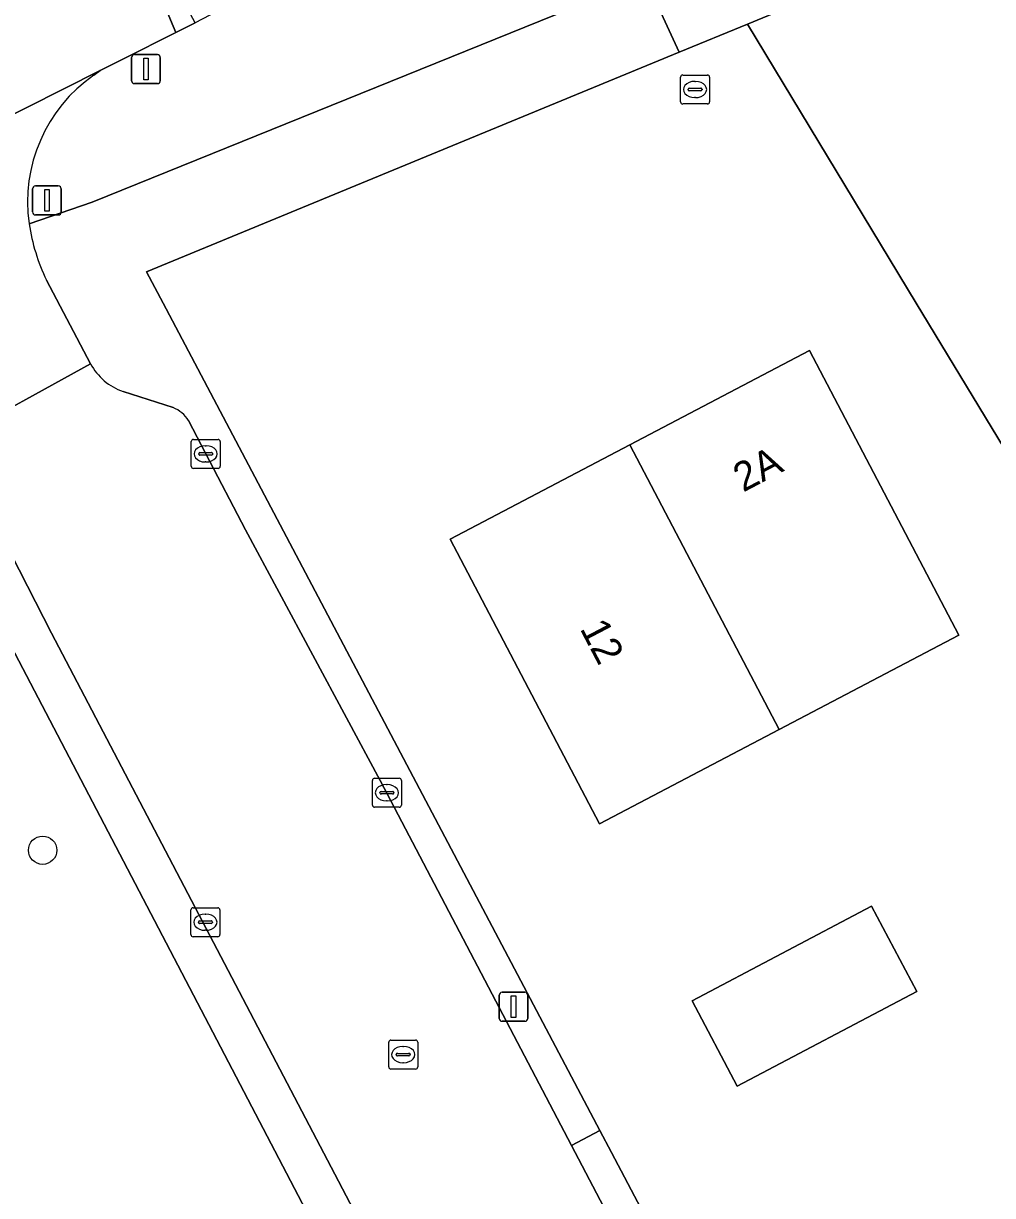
# Model space of a CAD drawing. Extents: x 162879 to 165540, y 384011 to 385181.
# Drawn here: x 163066.68 to 163100.12, y 384219.21 to 384259.65 of the extents above; entities that cross this region are included whole.
import ezdxf

# ---------------------------------------------------------------- set-up
doc = ezdxf.new("R2010")
doc.units = 0
for name, color, linetype in [('IMGEO_Boom', 7, 'Continuous'), ('IMGEO_Brandkraan', 7, 'Continuous'), ('IMGEO_Erf', 7, 'Continuous'), ('IMGEO_Groenvoorziening', 7, 'Continuous'), ('IMGEO_Kolk', 7, 'Continuous'), ('IMGEO_Lichtmast', 7, 'Continuous'), ('IMGEO_Loofbos', 7, 'Continuous'), ('IMGEO_Pand', 7, 'Continuous'), ('IMGEO_Pand_nummerreeks', 7, 'Continuous'), ('IMGEO_Rijbaan_lokaal_gesloten', 7, 'Continuous'), ('IMGEO_Rijbaan_lokaal_open', 7, 'Continuous'), ('IMGEO_Rioolput', 7, 'Continuous'), ('IMGEO_Verkeersbordpaal', 7, 'Continuous'), ('IMGEO_Voetpad_open', 7, 'Continuous')]:
    doc.layers.add(name, color=color, linetype=linetype)

msp = doc.modelspace()

# ---------------------------------------------------------------- linework, layer by layer
at = {"layer": 'IMGEO_Boom'}
msp.add_circle((163067.341, 384231.127), 0.489, dxfattribs=at)
at = {"layer": 'IMGEO_Brandkraan'}
for p, q in [((163089.356, 384256.945), (163089.356, 384257.797)), ((163089.431, 384257.871), (163090.283, 384257.871)), ((163089.844, 384257.651), (163089.869, 384257.651)), ((163090.357, 384257.797), (163090.357, 384256.945)), ((163089.615, 384257.365), (163089.615, 384257.377)), ((163090.053, 384257.328), (163089.655, 384257.328)), ((163089.658, 384257.414), (163090.056, 384257.414)), ((163090.099, 384257.377), (163090.099, 384257.365)), ((163090.283, 384256.871), (163089.431, 384256.871)), ((163089.867, 384257.091), (163089.842, 384257.091))]:
    msp.add_line(p, q, dxfattribs=at)
for points in [[(163089.356, 384256.945), (163089.356, 384257.797)], [(163089.431, 384257.871), (163090.283, 384257.871)], [(163090.357, 384257.797), (163090.357, 384256.945)], [(163090.283, 384256.871), (163089.431, 384256.871)]]:
    msp.add_lwpolyline(points, dxfattribs=at)
for centre, radius, start, end in [((163089.433, 384257.795), 0.0765, 91.552, 178.448), ((163089.433, 384257.795), 0.0765, 91.552, 178.448), ((163090.281, 384257.795), 0.0765, 1.552, 88.448), ((163090.281, 384257.795), 0.0765, 1.552, 88.448), ((163089.655, 384257.374), 0.0403, 85.8775, 175.7526), ((163089.652, 384257.364), 0.0366, 178.938, 274.7102), ((163090.056, 384257.371), 0.043, 264.8664, 352.4533), ((163090.06, 384257.376), 0.0386, 1.7309, 96.639), ((163089.433, 384256.947), 0.0765, 181.552, 268.448), ((163089.433, 384256.947), 0.0765, 181.552, 268.448), ((163090.281, 384256.947), 0.0765, 271.552, 358.448), ((163090.281, 384256.947), 0.0765, 271.552, 358.448)]:
    msp.add_arc(centre, radius, start, end, dxfattribs=at)
for centre, major_axis, ratio, start_param, end_param in [((163089.843, 384257.371), (-0.387, 0.002), 0.722429, 4.712389, 7.853982), ((163089.868, 384257.371), (-0.39, 0.002), 0.717154, 1.570796, 4.712389)]:
    msp.add_ellipse(centre, major_axis=major_axis, ratio=ratio, start_param=start_param, end_param=end_param, dxfattribs=at)
at = {"layer": 'IMGEO_Erf'}
for points in [[(163102.346, 384234.16), (163102.432, 384234.205), (163100.651, 384237.577), (163103.837, 384239.259), (163105.617, 384235.887), (163105.946, 384236.061), (163097.491, 384250), (163091.662, 384259.624), (163089.311, 384258.655), (163070.929, 384251.083), (163071.501, 384250), (163086.567, 384221.458), (163086.969, 384220.697), (163092.948, 384209.374), (163113.929, 384219.667), (163114.138, 384219.769), (163111.612, 384224.762), (163108.882, 384230.159), (163105.424, 384228.333)], [(163092.76, 384235.29), (163086.556, 384232.036), (163081.402, 384241.862), (163087.605, 384245.115), (163093.808, 384248.369), (163098.962, 384238.543)], [(163097.505, 384226.251), (163091.306, 384222.983), (163089.754, 384225.927), (163095.95, 384229.2)]]:
    msp.add_lwpolyline(points, close=True, dxfattribs=at)
at = {"layer": 'IMGEO_Groenvoorziening'}
for points in [[(163088.136, 384261.216), (163086.443, 384265.31), (163074.285, 384260.44), (163073.374, 384260.069), (163072.602, 384259.676), (163071.935, 384259.339), (163070.11, 384258.418), (163069.325, 384258.023), (163069.104, 384257.867)], [(163066.874, 384252.737), (163069.054, 384253.483), (163088.136, 384261.216)]]:
    msp.add_lwpolyline(points, dxfattribs=at)
msp.add_lwpolyline([(163062.352, 384245.606), (163049.969, 384239.189), (163051.264, 384236.696), (163047.577, 384234.747), (163057.039, 384216.873), (163041.173, 384208.482), (163044.864, 384201.274), (163071.063, 384215.12), (163072.147, 384212.977), (163072.222, 384213.017), (163074.076, 384209.512), (163077.812, 384211.477), (163079.73, 384207.94), (163081.516, 384208.957)], close=True, dxfattribs=at)
msp.add_arc((163072.162, 384253.488), 5.341, 124.9288, 188.0822, dxfattribs=at)
at = {"layer": 'IMGEO_Kolk'}
for p, q in [((163072.468, 384244.375), (163072.468, 384245.227)), ((163072.543, 384245.301), (163073.395, 384245.301)), ((163073.469, 384245.227), (163073.469, 384244.375)), ((163072.727, 384244.795), (163072.727, 384244.807)), ((163073.165, 384244.758), (163072.767, 384244.758)), ((163072.77, 384244.844), (163073.168, 384244.844)), ((163072.956, 384245.081), (163072.981, 384245.081)), ((163073.211, 384244.807), (163073.211, 384244.795)), ((163073.395, 384244.301), (163072.543, 384244.301)), ((163072.979, 384244.521), (163072.954, 384244.521)), ((163078.722, 384232.684), (163078.722, 384233.536)), ((163078.797, 384233.61), (163079.649, 384233.61)), ((163079.21, 384233.39), (163079.235, 384233.39)), ((163079.723, 384233.536), (163079.723, 384232.684)), ((163078.981, 384233.104), (163078.981, 384233.116)), ((163079.419, 384233.067), (163079.021, 384233.067)), ((163079.024, 384233.153), (163079.422, 384233.153)), ((163079.465, 384233.116), (163079.465, 384233.104)), ((163079.649, 384232.61), (163078.797, 384232.61)), ((163079.233, 384232.83), (163079.208, 384232.83)), ((163072.458, 384228.218), (163072.458, 384229.07)), ((163072.533, 384229.144), (163073.385, 384229.144)), ((163072.946, 384228.924), (163072.971, 384228.924)), ((163073.459, 384229.07), (163073.459, 384228.218)), ((163072.717, 384228.638), (163072.717, 384228.65)), ((163073.155, 384228.601), (163072.757, 384228.601)), ((163072.76, 384228.687), (163073.158, 384228.687)), ((163073.201, 384228.65), (163073.201, 384228.638)), ((163073.385, 384228.144), (163072.533, 384228.144)), ((163072.969, 384228.364), (163072.944, 384228.364))]:
    msp.add_line(p, q, dxfattribs=at)
for points in [[(163072.468, 384244.375), (163072.468, 384245.227)], [(163072.543, 384245.301), (163073.395, 384245.301)], [(163073.469, 384245.227), (163073.469, 384244.375)], [(163073.395, 384244.301), (163072.543, 384244.301)], [(163078.722, 384232.684), (163078.722, 384233.536)], [(163078.797, 384233.61), (163079.649, 384233.61)], [(163079.723, 384233.536), (163079.723, 384232.684)], [(163079.649, 384232.61), (163078.797, 384232.61)], [(163072.458, 384228.218), (163072.458, 384229.07)], [(163072.533, 384229.144), (163073.385, 384229.144)], [(163073.459, 384229.07), (163073.459, 384228.218)], [(163073.385, 384228.144), (163072.533, 384228.144)]]:
    msp.add_lwpolyline(points, dxfattribs=at)
for centre, radius, start, end in [((163072.545, 384245.225), 0.0765, 91.552, 178.448), ((163072.545, 384245.225), 0.0765, 91.552, 178.448), ((163073.393, 384245.225), 0.0765, 1.552, 88.448), ((163073.393, 384245.225), 0.0765, 1.552, 88.448), ((163072.767, 384244.804), 0.0403, 85.8775, 175.7526), ((163072.764, 384244.794), 0.0366, 178.938, 274.7102), ((163073.168, 384244.801), 0.043, 264.8664, 352.4533), ((163073.172, 384244.806), 0.0386, 1.7309, 96.639), ((163072.545, 384244.377), 0.0765, 181.552, 268.448), ((163072.545, 384244.377), 0.0765, 181.552, 268.448), ((163073.393, 384244.377), 0.0765, 271.552, 358.448), ((163073.393, 384244.377), 0.0765, 271.552, 358.448), ((163078.799, 384233.534), 0.0765, 91.552, 178.448), ((163078.799, 384233.534), 0.0765, 91.552, 178.448), ((163079.647, 384233.534), 0.0765, 1.552, 88.448), ((163079.647, 384233.534), 0.0765, 1.552, 88.448), ((163079.021, 384233.113), 0.0403, 85.8775, 175.7526), ((163079.018, 384233.103), 0.0366, 178.938, 274.7102), ((163079.422, 384233.11), 0.043, 264.8664, 352.4533), ((163079.426, 384233.115), 0.0386, 1.7309, 96.639), ((163078.799, 384232.686), 0.0765, 181.552, 268.448), ((163078.799, 384232.686), 0.0765, 181.552, 268.448), ((163079.647, 384232.686), 0.0765, 271.552, 358.448), ((163079.647, 384232.686), 0.0765, 271.552, 358.448), ((163072.535, 384229.068), 0.0765, 91.552, 178.448), ((163072.535, 384229.068), 0.0765, 91.552, 178.448), ((163073.383, 384229.068), 0.0765, 1.552, 88.448), ((163073.383, 384229.068), 0.0765, 1.552, 88.448), ((163072.757, 384228.647), 0.0403, 85.8775, 175.7526), ((163072.754, 384228.637), 0.0366, 178.938, 274.7102), ((163073.158, 384228.644), 0.043, 264.8664, 352.4533), ((163073.162, 384228.649), 0.0386, 1.7309, 96.639), ((163072.535, 384228.22), 0.0765, 181.552, 268.448), ((163072.535, 384228.22), 0.0765, 181.552, 268.448), ((163073.383, 384228.22), 0.0765, 271.552, 358.448), ((163073.383, 384228.22), 0.0765, 271.552, 358.448)]:
    msp.add_arc(centre, radius, start, end, dxfattribs=at)
for centre, major_axis, ratio, start_param, end_param in [((163072.955, 384244.801), (-0.387, 0.002), 0.722429, 4.712389, 7.853982), ((163072.98, 384244.801), (-0.39, 0.002), 0.717154, 1.570796, 4.712389), ((163079.209, 384233.11), (-0.387, 0.002), 0.722429, 4.712389, 7.853982), ((163079.234, 384233.11), (-0.39, 0.002), 0.717154, 1.570796, 4.712389), ((163072.945, 384228.644), (-0.387, 0.002), 0.722429, 4.712389, 7.853982), ((163072.97, 384228.644), (-0.39, 0.002), 0.717154, 1.570796, 4.712389)]:
    msp.add_ellipse(centre, major_axis=major_axis, ratio=ratio, start_param=start_param, end_param=end_param, dxfattribs=at)
at = {"layer": 'IMGEO_Lichtmast'}
for p, q in [((163083.096, 384225.327), (163083.096, 384226.127)), ((163083.096, 384226.127), (163083.096, 384225.327)), ((163083.196, 384226.227), (163083.986, 384226.227)), ((163083.986, 384226.227), (163083.196, 384226.227)), ((163084.086, 384226.127), (163084.086, 384225.327)), ((163084.086, 384225.327), (163084.086, 384226.127)), ((163083.986, 384225.227), (163083.196, 384225.227)), ((163083.196, 384225.227), (163083.986, 384225.227))]:
    msp.add_line(p, q, dxfattribs=at)
msp.add_lwpolyline([(163083.516, 384226.102), (163083.666, 384226.102), (163083.666, 384225.352), (163083.516, 384225.352), (163083.516, 384226.102)], dxfattribs=at)
for centre, start, end in [((163083.196, 384226.127), 90, 180), ((163083.196, 384226.127), 90, 180), ((163083.986, 384226.127), 0, 90), ((163083.986, 384226.127), 360, 90), ((163083.196, 384225.327), 180, 270), ((163083.196, 384225.327), 180, 270), ((163083.986, 384225.327), 270, 0), ((163083.986, 384225.327), 270, 0)]:
    msp.add_arc(centre, 0.1, start, end, dxfattribs=at)
at = {"layer": 'IMGEO_Loofbos'}
msp.add_lwpolyline([(163155.934, 384258.131), (163155.116, 384260.952), (163148.784, 384282.785), (163112.465, 384268.23), (163091.662, 384259.624), (163097.491, 384250), (163105.946, 384236.061), (163109.025, 384230.235), (163114.501, 384233.625), (163136.641, 384247.33), (163140.262, 384250), (163143.861, 384252.646)], close=True, dxfattribs=at)
at = {"layer": 'IMGEO_Pand'}
for points in [[(163092.76, 384235.29), (163098.962, 384238.543), (163093.808, 384248.369), (163087.605, 384245.115)], [(163092.76, 384235.29), (163087.605, 384245.115), (163081.402, 384241.862), (163086.556, 384232.036)], [(163095.95, 384229.2), (163089.754, 384225.927), (163091.306, 384222.983), (163097.505, 384226.251)]]:
    msp.add_lwpolyline(points, close=True, dxfattribs=at)
at = {"layer": 'IMGEO_Rijbaan_lokaal_gesloten'}
msp.add_lwpolyline([(163093.642, 384273.04), (163070.882, 384263.789), (163070.704, 384264.278), (163069.992, 384263.975), (163071.935, 384259.339), (163072.602, 384259.676), (163072.365, 384260.115), (163073.136, 384260.517), (163073.968, 384260.869), (163074.82, 384261.212), (163086.237, 384265.783), (163101.219, 384271.839)], dxfattribs=at)
msp.add_lwpolyline([(163069.325, 384258.023), (163070.11, 384258.418), (163071.935, 384259.339), (163069.992, 384263.975), (163060.533, 384260.029), (163050.998, 384256.102), (163049.129, 384255.319), (163048.235, 384254.869), (163047.128, 384254.295), (163035.025, 384248.253), (163031.406, 384246.417), (163034.42, 384240.509), (163038.44, 384242.526), (163056.687, 384251.652)], close=True, dxfattribs=at)
at = {"layer": 'IMGEO_Rijbaan_lokaal_open'}
for points in [[(163069.104, 384257.867), (163069.325, 384258.023), (163056.687, 384251.652)], [(163063.465, 384246.618), (163064.184, 384245.26), (163068.997, 384247.911), (163067.475, 384250.797)], [(163068.997, 384247.911), (163064.184, 384245.26), (163065.688, 384242.421), (163067.65, 384238.621), (163098.898, 384178.954), (163107.986, 384161.625), (163108.767, 384160.138)], [(163071.846, 384246.395), (163070.118, 384246.951)], [(163123.456, 384148.995), (163120.518, 384154.619), (163109.182, 384176.32), (163104.407, 384185.46), (163103.99, 384186.246), (163098.666, 384196.282), (163094.956, 384203.096), (163085.593, 384220.946), (163078.99, 384233.534), (163074.347, 384242.176), (163072.969, 384244.801), (163072.377, 384245.947)]]:
    msp.add_lwpolyline(points, dxfattribs=at)
for centre, radius, start, end in [((163072.162, 384253.488), 5.341, 124.9288, 188.0822), ((163073.531, 384253.736), 6.731, 188.5358, 205.8895), ((163070.769, 384248.846), 2.003, 207.8079, 251.04), ((163071.416, 384245.347), 1.133, 31.9921, 67.6998)]:
    msp.add_arc(centre, radius, start, end, dxfattribs=at)
at = {"layer": 'IMGEO_Rioolput'}
for p, q in [((163079.285, 384223.651), (163079.285, 384224.503)), ((163079.36, 384224.577), (163080.212, 384224.577)), ((163080.286, 384224.503), (163080.286, 384223.651)), ((163079.544, 384224.071), (163079.544, 384224.083)), ((163079.587, 384224.12), (163079.985, 384224.12)), ((163079.773, 384224.357), (163079.798, 384224.357)), ((163080.028, 384224.083), (163080.028, 384224.071)), ((163079.982, 384224.034), (163079.584, 384224.034)), ((163079.796, 384223.797), (163079.771, 384223.797)), ((163080.212, 384223.577), (163079.36, 384223.577))]:
    msp.add_line(p, q, dxfattribs=at)
for points in [[(163079.285, 384223.651), (163079.285, 384224.503)], [(163079.36, 384224.577), (163080.212, 384224.577)], [(163080.286, 384224.503), (163080.286, 384223.651)], [(163080.212, 384223.577), (163079.36, 384223.577)]]:
    msp.add_lwpolyline(points, dxfattribs=at)
for centre, radius, start, end in [((163079.362, 384224.501), 0.0765, 91.552, 178.448), ((163079.362, 384224.501), 0.0765, 91.552, 178.448), ((163080.21, 384224.501), 0.0765, 1.552, 88.448), ((163080.21, 384224.501), 0.0765, 1.552, 88.448), ((163079.584, 384224.08), 0.0403, 85.8775, 175.7526), ((163079.581, 384224.07), 0.0366, 178.938, 274.7102), ((163079.985, 384224.077), 0.043, 264.8664, 352.4533), ((163079.989, 384224.082), 0.0386, 1.7309, 96.639), ((163079.362, 384223.653), 0.0765, 181.552, 268.448), ((163079.362, 384223.653), 0.0765, 181.552, 268.448), ((163080.21, 384223.653), 0.0765, 271.552, 358.448), ((163080.21, 384223.653), 0.0765, 271.552, 358.448)]:
    msp.add_arc(centre, radius, start, end, dxfattribs=at)
for centre, major_axis, ratio, start_param, end_param in [((163079.772, 384224.077), (-0.387, 0.002), 0.722429, 4.712389, 7.853982), ((163079.797, 384224.077), (-0.39, 0.002), 0.717154, 1.570796, 4.712389)]:
    msp.add_ellipse(centre, major_axis=major_axis, ratio=ratio, start_param=start_param, end_param=end_param, dxfattribs=at)
at = {"layer": 'IMGEO_Verkeersbordpaal'}
for p, q in [((163070.41, 384257.674), (163070.41, 384258.474)), ((163070.41, 384258.474), (163070.41, 384257.674)), ((163070.51, 384258.574), (163071.3, 384258.574)), ((163071.3, 384258.574), (163070.51, 384258.574)), ((163071.4, 384258.474), (163071.4, 384257.674)), ((163071.4, 384257.674), (163071.4, 384258.474)), ((163071.3, 384257.574), (163070.51, 384257.574)), ((163070.51, 384257.574), (163071.3, 384257.574)), ((163067.092, 384254.045), (163067.882, 384254.045)), ((163067.882, 384254.045), (163067.092, 384254.045)), ((163066.992, 384253.145), (163066.992, 384253.945)), ((163066.992, 384253.945), (163066.992, 384253.145)), ((163067.982, 384253.945), (163067.982, 384253.145)), ((163067.982, 384253.145), (163067.982, 384253.945)), ((163067.882, 384253.045), (163067.092, 384253.045)), ((163067.092, 384253.045), (163067.882, 384253.045))]:
    msp.add_line(p, q, dxfattribs=at)
for points in [[(163070.83, 384258.449), (163070.98, 384258.449), (163070.98, 384257.699), (163070.83, 384257.699), (163070.83, 384258.449)], [(163067.412, 384253.92), (163067.562, 384253.92), (163067.562, 384253.17), (163067.412, 384253.17), (163067.412, 384253.92)]]:
    msp.add_lwpolyline(points, dxfattribs=at)
for centre, start, end in [((163070.51, 384258.474), 90, 180), ((163070.51, 384258.474), 90, 180), ((163071.3, 384258.474), 0, 90), ((163071.3, 384258.474), 360, 90), ((163070.51, 384257.674), 180, 270), ((163070.51, 384257.674), 180, 270), ((163071.3, 384257.674), 270, 0), ((163071.3, 384257.674), 270, 0), ((163067.092, 384253.945), 90, 180), ((163067.092, 384253.945), 90, 180), ((163067.882, 384253.945), 0, 90), ((163067.882, 384253.945), 360, 90), ((163067.092, 384253.145), 180, 270), ((163067.092, 384253.145), 180, 270), ((163067.882, 384253.145), 270, 0), ((163067.882, 384253.145), 270, 0)]:
    msp.add_arc(centre, 0.1, start, end, dxfattribs=at)
at = {"layer": 'IMGEO_Voetpad_open'}
for points in [[(163148.784, 384282.785), (163154.745, 384282.736), (163153.346, 384287.562), (163148.014, 384285.572), (163114.146, 384272.104), (163100.027, 384266.274), (163091.511, 384262.562), (163089.844, 384266.648), (163086.443, 384265.31), (163088.136, 384261.216), (163089.311, 384258.655), (163091.662, 384259.624), (163112.465, 384268.23)], [(163092.948, 384209.374), (163086.969, 384220.697), (163086.567, 384221.458), (163085.593, 384220.946), (163094.956, 384203.096), (163098.666, 384196.282), (163099.596, 384196.782)]]:
    msp.add_lwpolyline(points, close=True, dxfattribs=at)
for points in [[(163089.311, 384258.655), (163088.136, 384261.216), (163069.054, 384253.483), (163066.874, 384252.737)], [(163072.377, 384245.947), (163072.969, 384244.801), (163074.347, 384242.176), (163078.99, 384233.534), (163085.593, 384220.946), (163086.567, 384221.458), (163071.501, 384250), (163070.929, 384251.083), (163089.311, 384258.655)], [(163067.475, 384250.797), (163068.997, 384247.911)], [(163070.118, 384246.951), (163071.846, 384246.395)], [(163067.65, 384238.621), (163065.688, 384242.421), (163064.184, 384245.26), (163062.352, 384245.606), (163081.516, 384208.957), (163082.45, 384207.161), (163097.509, 384178.219), (163099.858, 384173.768), (163108.593, 384157.219), (163108.822, 384157.894)], [(163108.767, 384160.138), (163107.986, 384161.625), (163098.898, 384178.954), (163067.65, 384238.621)]]:
    msp.add_lwpolyline(points, dxfattribs=at)
for centre, radius, start, end in [((163073.531, 384253.736), 6.731, 188.5358, 205.8895), ((163070.769, 384248.846), 2.003, 207.8079, 251.04), ((163071.416, 384245.347), 1.133, 31.9921, 67.6998)]:
    msp.add_arc(centre, radius, start, end, dxfattribs=at)

# ---------------------------------------------------------------- texts
at = {"layer": 'IMGEO_Pand_nummerreeks'}
for s, rotation, p in [('2A', 27.6772, (163091.517, 384243.464)), ('12', 297.6782, (163085.867, 384238.774))]:
    msp.add_text(s, height=1, rotation=rotation, dxfattribs=at).set_placement(p)

doc.saveas('drawing.dxf')
